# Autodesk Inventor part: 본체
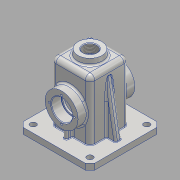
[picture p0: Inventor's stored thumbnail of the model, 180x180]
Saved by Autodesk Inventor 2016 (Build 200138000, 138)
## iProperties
Created: 2018-10
Part Number: 본체
Material: 알루미늄 6061
Document SubType Name: Modeling
Designer: user
Density: 2.7 g/cm^3
Appearance: 알루미늄 - 평지
Mass: 794.227 g
Surface Area: 899.5 cm^2
Volume: 294.158 cm^3
Author: user
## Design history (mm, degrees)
sketch "스케치1"
  geometry: L1 (60, -60)-(-60, -60); L2 (-60, -60)-(-60, 60); L3 (-60, 60)-(60, 60); L4 (60, 60)-(60, -60); L5 (60, -60)-(-60, 60); L6 (-60, -60)-(60, 60); 1 further point
  constraints: 12 end point, 2 midpoint, 2 parallel, 1 horizontal, 1 perpendicular
  dimensions: "d0" = 120 distance of L2.end L3.end; "d1" = 120 distance of L1.end L2.end
extrude "돌출1" new body sketch "스케치1" distance "d2" = 10; taper "d3" = 0 deg
chamfer "모따기1" distance "d4" = 8; stored, may be unused: second distance "d5" = 2, angle "d6" = 45 deg
sketch "스케치2"
  geometry: L1 (47.5, -47.5)-(-47.5, -47.5); L2 (-47.5, -47.5)-(-47.5, 47.5); L3 (-47.5, 47.5)-(47.5, 47.5); L4 (47.5, 47.5)-(47.5, -47.5); L5 (47.5, -47.5)-(-47.5, 47.5); L6 (-47.5, -47.5)-(47.5, 47.5); 5 further points
  constraints: 12 end point, 4 coincident, 2 midpoint, 2 parallel, 1 horizontal, 1 perpendicular
  dimensions: "d7" = 95 distance of L2.end L3.end; "d8" = 95 distance of L1.end L2.end
hole "구멍1" sketch "스케치2" at (-47.5, 47.5), (47.5, 47.5), (47.5, -47.5), (-47.5, -47.5) diameter "d9" = 10; stored, may be unused: countersink angle "d13" = 90 deg, drill point angle "d15" = 118 deg; dims "d10" = 6, "d11" = 4, "d12" = 2, "d14" = 8
sketch "스케치3"
  geometry: L1 (-32.5, -32.5)-(32.5, -32.5); L2 (32.5, -32.5)-(32.5, 32.5); L3 (32.5, 32.5)-(-32.5, 32.5); L4 (-32.5, 32.5)-(-32.5, -32.5); L5 (-32.5, -32.5)-(32.5, 32.5); L6 (32.5, -32.5)-(-32.5, 32.5); 1 further point
  constraints: 12 end point, 2 midpoint, 2 parallel, 1 horizontal, 1 perpendicular
  dimensions: "d16" = 65 distance of L2.end L3.end; "d17" = 65 distance of L3.end L1.start
extrude "돌출2" join sketch "스케치3" distance "d18" = 100; taper "d19" = 0 deg
sketch "스케치4"
  geometry: C1 r 20 at (0, 0); 1 further point
  constraints: 1 centre point, 1 coincident
  dimensions: "d20" = 40 diameter of C1
extrude "돌출3" join sketch "스케치4" distance "d21" = 10; taper "d22" = 0 deg
sketch "스케치5"
  geometry: C1 r 20 at (0, 0) reference; C2 r 20 at (0, 0) reference
extrude "돌출4" join sketch "스케치5" distance "d23" = 10; taper "d24" = 7 deg
sketch "스케치6"
  geometry: L1 (27.5, -27.5)-(-27.5, -27.5); L2 (-27.5, -27.5)-(-27.5, 27.5); L3 (-27.5, 27.5)-(27.5, 27.5); L4 (27.5, 27.5)-(27.5, -27.5); L5 (27.5, -27.5)-(-27.5, 27.5); L6 (-27.5, -27.5)-(27.5, 27.5); 1 further point
  constraints: 12 end point, 2 midpoint, 2 parallel, 1 horizontal, 1 perpendicular
  dimensions: "d25" = 55 distance of L1.end L2.end; "d26" = 55 distance of L1.start L1.end
extrude "돌출5" cut sketch "스케치6" distance "d27" = 105; taper "d28" = 0 deg
sketch "스케치7"
  geometry: L1 (84.5, -10)-(-19.5, -10) reference; L2 (-19.5, 0)-(84.5, 0) reference; C1 r 27.5 at (32.5, 45); 2 further points
  constraints: 1 centre point, 1 midpoint, 1 vertical alignment
  dimensions: "d29" = 55 distance from line of L1 C1.centre; "d30" = 55 diameter of C1
extrude "돌출6" join sketch "스케치7" distance "d31" = 15; taper "d32" = 0 deg
hole "구멍2" diameter "d35" = 30; stored, may be unused: countersink angle "d39" = 90 deg, drill point angle "d41" = 118 deg; dims "d33" = 10, "d34" = 10, "d36" = 22.225, "d37" = 35, "d38" = 17, "d40" = 8
sketch "스케치8"
  geometry: C1 r 17.5 at (0, 0) reference; 2 further points
  constraints: 1 vertical alignment
  dimensions: "d42" = 21 distance of C1.centre point (0, 21)
hole "구멍3" sketch "스케치8" at (0, 21) diameter "d43" = 3.242; stored, may be unused: countersink angle "d47" = 90 deg, drill point angle "d49" = 118 deg; dims "d44" = 8, "d45" = 35, "d46" = 17, "d48" = 10
node "작업 평면1"
hole "구멍4" diameter "d55" = 22.835; stored, may be unused: countersink angle "d59" = 90 deg, drill point angle "d61" = 118 deg; dims "d53" = 10, "d54" = 10, "d56" = 50, "d57" = 35, "d58" = 17, "d60" = 59.3
sketch "스케치9"
  geometry: L1 (0, 0)-(0, 100) reference; L2 (0, 100)-(11.272, 100) reference; L3 (11.272, 100)-(12.5, 110) reference; L4 (12.5, 110)-(21.083, 110) reference; L5 (21.083, 110)-(21.083, 95) reference; L6 (21.083, 95)-(5, 95) reference; L7 (5, 95)-(5, -10) reference; L8 (5, -10)-(-27.5, -10) reference; L9 (-27.5, -10)-(-27.5, 0) reference; L10 (-27.5, 0)-(0, 0) reference; L11 (65, 100)-(65, 0) reference; L12 (65, 0)-(92.5, 0) reference; L13 (92.5, 0)-(92.5, -10) reference; L14 (92.5, -10)-(60, -10) reference; L15 (60, -10)-(60, 95) reference; L16 (60, 95)-(43.918, 95) reference; L17 (43.918, 95)-(43.918, 110) reference; L18 (43.918, 110)-(52.5, 110) reference; L19 (52.5, 110)-(53.728, 100) reference; L20 (53.728, 100)-(65, 100) reference; L21 (0, 0)-(0, 100) reference; L22 (0, 87.905)-(-15.5, 0); 1 further point
  constraints: 2 end point, 2 point on line
  dimensions: "d62" = 12 distance from line of L9 L22.end; "d63" = 10 deg angle of L9 L22
extrude "돌출7" join sketch "스케치9" stored distance "d64" = 10; taper "d65" = 0 deg
node "작업 평면2"
sketch "스케치10"
  geometry: L1 (-3, -42.5)-(3, -42.5); L2 (3, -42.5)-(3, -27.5); L3 (3, -27.5)-(-3, -27.5); L4 (-3, -27.5)-(-3, -42.5); L5 (-27.5, -27.5)-(27.5, -27.5) reference; 2 further points
  constraints: 8 end point, 2 midpoint, 2 parallel, 1 horizontal, 1 perpendicular
  dimensions: "d66" = 6 distance of L1.start L1.end; "d67" = 15 distance of L3.end L1.start
extrude "돌출8" join sketch "스케치10" stored distance "d68" = 10; taper "d69" = 0 deg
fillet "모깎기1" dims "d70" = 8
fillet "모깎기2" dims "d71" = 8
fillet "모깎기3" dims "d72" = 3
fillet "모깎기4" dims "d73" = 3
fillet "모깎기5" dims "d74" = 3
fillet "모깎기6" dims "d75" = 1
fillet "모깎기7" dims "d76" = 3
fillet "모깎기8" dims "d77" = 0.3
chamfer "모따기2" distance "d78" = 1; stored, may be unused: second distance "d79" = 2, angle "d80" = 45 deg
sketch "스케치11"
  geometry: L1 (4.5, -18)-(44.5, -18) reference; L2 (57, 0)-(57, 91) reference; 2 further points
  constraints: 1 other
  dimensions: "d81" = 26 distance from line of L1 point (24.5, 8); "d82" = 32.5 distance from line of L2 point (24.5, 8)
feature "엠보싱1" sketch "스케치11" dims "d9" = 10, "d11" = 4, "d12" = 2, "d14" = 8, "d83" = 0.5, "d84" = 0
node "솔리드1"
pattern_circular "원형 패턴1" dims angle "d51" = 360 deg
mirror "대칭1"
mirror "대칭2"
mirror "대칭3"
node "투영된 루프1"
node "절단 모서리 투영1"
